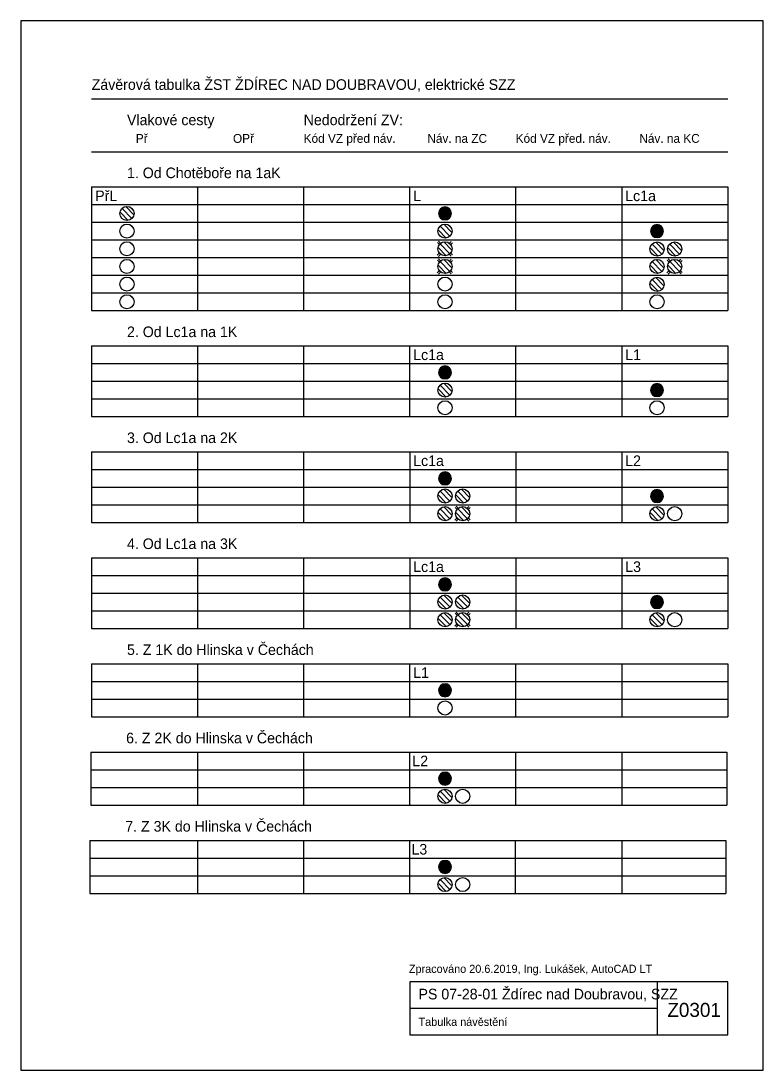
# Model space of a CAD drawing. Extents: x 2343 to 5155, y -3940 to 2050.
# Drawn here: x 3920 to 4130, y -3940 to -3643 of the extents above; entities that cross this region are included whole.
import ezdxf

# ---------------------------------------------------------------- set-up
doc = ezdxf.new("R2010")
doc.units = 0
for name, color, linetype in [('0B', 7, 'Continuous'), ('Implicitní', 7, 'Continuous'), ('Vrstva 63', 7, 'Continuous')]:
    doc.layers.add(name, color=color, linetype=linetype)

# ---------------------------------------------------------------- blocks, each defined once
blk = doc.blocks.new('ZT75')
at = {"layer": 'Implicitní'}
for points in [[(-18.1, 3.2), (18.1, 3.2)], [(-17.6, 0.7), (17.6, 0.7)], [(-17.3, 6.4), (17.3, 6.4)], [(-15.7, 9.6), (15.7, 9.6)], [(-14, 12), (14, 12)], [(-12.4, 13.6), (12.4, 13.6)], [(-10.4, 15.2), (10.4, 15.2)], [(-7.6, 16.8), (7.6, 16.8)], [(-18.1, -3.2), (18.1, -3.2)], [(-17.6, -0.7), (17.6, -0.7)], [(-17.3, -6.4), (17.3, -6.4)], [(-15.7, -9.6), (15.7, -9.6)], [(-14, -12), (14, -12)], [(-12.4, -13.6), (12.4, -13.6)], [(-10.4, -15.2), (10.4, -15.2)], [(-7.6, -16.8), (7.6, -16.8)]]:
    blk.add_lwpolyline(points, dxfattribs=at)
for start, end in [(0, 180), (180, 0)]:
    blk.add_arc((0, 0), 18.4, start, end, dxfattribs=at)
blk = doc.blocks.new('ZT76')
at = {"layer": 'Implicitní'}
for p, q in [((3.7, 19.7), (-19.7, -3.7)), ((14.1, 14.1), (-14.1, -14.1)), ((19.7, 3.7), (-3.7, -19.7))]:
    blk.add_line(p, q, dxfattribs=at)
blk.add_circle((0, 0), 20, dxfattribs=at)
blk = doc.blocks.new('ZT74')
at = {"layer": 'Implicitní'}
blk.add_circle((0, 0), 20, dxfattribs=at)
blk = doc.blocks.new('ZT78')
at = {"layer": 'Implicitní'}
for p, q in [((-30.7, 25.7), (-22.7, 17.7)), ((-25.7, 30.7), (-17.7, 22.7)), ((17.5, 21.7), (25.5, 29.7)), ((22.5, 16.7), (30.5, 24.7)), ((-31.3, -25.5), (-23.3, -17.5)), ((-26.3, -30.5), (-18.3, -22.5)), ((17.5, -21.7), (25.5, -29.7)), ((22.5, -16.7), (30.5, -24.7))]:
    blk.add_line(p, q, dxfattribs=at)

msp = doc.modelspace()

# ---------------------------------------------------------------- linework, layer by layer
at = {"layer": '0B'}
for p, q in [((3940, -3665), (4120, -3665)), ((3940, -3680), (4120, -3680)), ((3940, -3690), (4120, -3690)), ((3940, -3690), (3940, -3725)), ((3970, -3690), (3970, -3725)), ((4000, -3690), (4000, -3725)), ((4030, -3725), (4030, -3690)), ((4060, -3725), (4060, -3690)), ((4090, -3690), (4090, -3725)), ((4120, -3690), (4120, -3725)), ((3940, -3695), (4120, -3695)), ((3940, -3700), (4120, -3700)), ((3940, -3705), (4120, -3705)), ((3940, -3705), (4120, -3705)), ((3940, -3710), (4120, -3710)), ((3940, -3715), (4120, -3715)), ((3940, -3720), (4120, -3720)), ((3940, -3725), (4120, -3725)), ((3940, -3735), (4120, -3735)), ((3940, -3735), (3940, -3755)), ((3970, -3735), (3970, -3755)), ((4000, -3735), (4000, -3755)), ((4030, -3755), (4030, -3735)), ((4060, -3755), (4060, -3735)), ((4090, -3735), (4090, -3755)), ((4120, -3735), (4120, -3755)), ((3940, -3740), (4120, -3740)), ((3940, -3745), (4120, -3745)), ((3940, -3750), (4120, -3750)), ((3940, -3750), (4120, -3750)), ((3940, -3755), (4120, -3755)), ((3940, -3765), (4120, -3765)), ((3940, -3765), (3940, -3785)), ((3970, -3765), (3970, -3785)), ((4000, -3765), (4000, -3785)), ((4030, -3765), (4030, -3785)), ((4060, -3765), (4060, -3785)), ((4090, -3765), (4090, -3785)), ((4120, -3765), (4120, -3785)), ((3940, -3770), (4120, -3770)), ((3940, -3770), (4120, -3770)), ((3940, -3775), (4120, -3775)), ((3940, -3780), (4120, -3780)), ((3940, -3780), (4120, -3780)), ((3940, -3785), (4120, -3785)), ((3940, -3785), (4120, -3785)), ((3940, -3785), (4120, -3785)), ((3940, -3795), (4120, -3795)), ((3940, -3795), (3940, -3815)), ((3970, -3795), (3970, -3815)), ((4000, -3795), (4000, -3815)), ((4030, -3795), (4030, -3815)), ((4060, -3795), (4060, -3815)), ((4090, -3795), (4090, -3815)), ((4120, -3795), (4120, -3815)), ((3940, -3800), (4120, -3800)), ((3940, -3800), (4120, -3800)), ((3940, -3805), (4120, -3805)), ((3940, -3810), (4120, -3810)), ((3940, -3810), (4120, -3810)), ((3940, -3815), (4120, -3815)), ((3940, -3815), (4120, -3815)), ((3940, -3815), (4120, -3815)), ((3940, -3825), (4120, -3825)), ((3940, -3825), (3940, -3840)), ((3970, -3825), (3970, -3840)), ((4000, -3825), (4000, -3840)), ((4030, -3840), (4030, -3825)), ((4060, -3840), (4060, -3825)), ((4090, -3825), (4090, -3840)), ((4120, -3825), (4120, -3840)), ((3940, -3830), (4120, -3830)), ((3940, -3835), (4120, -3835)), ((3940, -3840), (4120, -3840)), ((3940, -3840), (4120, -3840)), ((3939.75, -3850), (4119.75, -3850)), ((3939.75, -3850), (3939.75, -3865)), ((3970, -3850), (3970, -3865)), ((4000, -3850), (4000, -3865)), ((4030, -3865), (4030, -3850)), ((4060, -3865), (4060, -3850)), ((4090, -3850), (4090, -3865)), ((4119.75, -3850), (4119.75, -3865)), ((3939.75, -3855), (4119.75, -3855)), ((3939.75, -3860), (4119.75, -3860)), ((3939.75, -3865), (4119.75, -3865)), ((3939.75, -3865), (4119.75, -3865)), ((3939.51, -3875), (4119.51, -3875)), ((3939.51, -3875), (3939.51, -3890)), ((3970, -3875), (3970, -3890)), ((4000, -3875), (4000, -3890)), ((4030, -3890), (4030, -3875)), ((4059.99, -3890), (4059.99, -3875)), ((4090, -3875), (4090, -3890)), ((4119.51, -3875), (4119.51, -3890)), ((3939.51, -3880), (4119.51, -3880)), ((3939.51, -3885), (4119.51, -3885)), ((3939.51, -3890), (4119.51, -3890)), ((3939.51, -3890), (4119.51, -3890)), ((4120, -3915), (4030, -3915)), ((4030, -3915), (4030, -3930)), ((4100, -3915), (4100, -3930)), ((4120, -3930), (4120, -3915)), ((4030, -3922.5), (4100, -3922.5)), ((4030, -3930), (4120, -3930))]:
    msp.add_line(p, q, dxfattribs=at)
at = {"layer": 'Vrstva 63'}
msp.add_lwpolyline([(3920, -3940), (4130, -3940), (4130, -3643), (3920, -3643)], close=True, dxfattribs=at)

# ---------------------------------------------------------------- block references
at = {"layer": '0B'}
for name, p, xscale, yscale, rotation in [('ZT76', (3950, -3697.5), 0.10000000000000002, 0.1, 89.99999999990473), ('ZT75', (4040, -3697.5), 0.1, 0.10000000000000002, -9.526953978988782e-11), ('ZT74', (3950, -3702.5), 0.1, 0.10000000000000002, -9.526953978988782e-11), ('ZT76', (4040, -3702.5), 0.10000000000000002, 0.1, 89.99999999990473), ('ZT75', (4100, -3702.5), 0.1, 0.10000000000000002, -9.526953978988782e-11), ('ZT74', (3950, -3707.5), 0.1, 0.10000000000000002, -9.526953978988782e-11), ('ZT78', (4040, -3707.5), 0.06999999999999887, 0.06999999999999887, -1.2050326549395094e-10), ('ZT76', (4040, -3707.5), 0.10000000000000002, 0.10000000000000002, 89.99999999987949), ('ZT76', (4100, -3707.57), 0.10000000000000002, 0.10000000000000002, 89.99999999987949), ('ZT76', (4105, -3707.57), 0.10000000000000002, 0.10000000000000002, 89.99999999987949), ('ZT74', (3950, -3712.5), 0.1, 0.10000000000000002, -9.526953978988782e-11), ('ZT78', (4040, -3712.5), 0.06999999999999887, 0.06999999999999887, -1.2050326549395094e-10), ('ZT76', (4040, -3712.5), 0.10000000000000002, 0.10000000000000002, 89.99999999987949), ('ZT76', (4040, -3712.5), 0.10000000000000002, 0.10000000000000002, 89.99999999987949), ('ZT76', (4100, -3712.5), 0.10000000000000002, 0.10000000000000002, 89.99999999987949), ('ZT78', (4105, -3712.5), 0.06999999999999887, 0.06999999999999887, -1.2050326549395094e-10), ('ZT76', (4105, -3712.5), 0.10000000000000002, 0.10000000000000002, 89.99999999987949), ('ZT76', (4105, -3712.5), 0.10000000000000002, 0.10000000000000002, 89.99999999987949), ('ZT74', (3950, -3717.5), 0.1, 0.10000000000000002, -9.526953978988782e-11), ('ZT74', (4040, -3717.5), 0.1, 0.10000000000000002, -9.526953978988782e-11), ('ZT76', (4100, -3717.57), 0.10000000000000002, 0.10000000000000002, 89.99999999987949), ('ZT74', (3950, -3722.5), 0.1, 0.10000000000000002, -9.526953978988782e-11), ('ZT74', (4040, -3722.5), 0.1, 0.10000000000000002, -9.526953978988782e-11), ('ZT74', (4100, -3722.5), 0.1, 0.10000000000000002, -9.526953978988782e-11), ('ZT75', (4040, -3742.5), 0.1, 0.10000000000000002, -9.526953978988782e-11), ('ZT76', (4040, -3747.5), 0.10000000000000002, 0.1, 89.99999999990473), ('ZT75', (4100, -3747.5), 0.1, 0.10000000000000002, -9.526953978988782e-11), ('ZT74', (4040, -3752.5), 0.1, 0.10000000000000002, -9.526953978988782e-11), ('ZT74', (4100, -3752.5), 0.1, 0.10000000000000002, -9.526953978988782e-11), ('ZT75', (4040, -3772.5), 0.1, 0.10000000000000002, -1.2050326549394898e-10), ('ZT76', (4040, -3777.5), 0.10000000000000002, 0.10000000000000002, 89.99999999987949), ('ZT76', (4045, -3777.5), 0.10000000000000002, 0.10000000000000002, 89.99999999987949), ('ZT76', (4045, -3777.5), 0.10000000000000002, 0.10000000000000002, 89.99999999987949), ('ZT75', (4100, -3777.5), 0.1, 0.10000000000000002, -1.2050326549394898e-10), ('ZT76', (4040, -3782.5), 0.10000000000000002, 0.10000000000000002, 89.99999999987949), ('ZT78', (4045, -3782.5), 0.06999999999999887, 0.06999999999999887, -1.2050326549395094e-10), ('ZT76', (4045, -3782.5), 0.10000000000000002, 0.10000000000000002, 89.99999999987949), ('ZT76', (4045, -3782.5), 0.10000000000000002, 0.10000000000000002, 89.99999999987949), ('ZT76', (4100, -3782.5), 0.10000000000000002, 0.10000000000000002, 89.99999999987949), ('ZT74', (4105, -3782.5), 0.1, 0.10000000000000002, -1.2050326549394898e-10), ('ZT75', (4040, -3802.5), 0.1, 0.10000000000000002, -1.2050326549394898e-10), ('ZT76', (4040, -3807.5), 0.10000000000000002, 0.10000000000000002, 89.99999999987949), ('ZT76', (4045, -3807.5), 0.10000000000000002, 0.10000000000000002, 89.99999999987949), ('ZT76', (4045, -3807.5), 0.10000000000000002, 0.10000000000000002, 89.99999999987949), ('ZT75', (4100, -3807.5), 0.1, 0.10000000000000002, -1.2050326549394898e-10), ('ZT76', (4040, -3812.5), 0.10000000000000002, 0.10000000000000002, 89.99999999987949), ('ZT78', (4045, -3812.5), 0.06999999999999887, 0.06999999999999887, -1.2050326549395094e-10), ('ZT76', (4045, -3812.5), 0.10000000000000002, 0.10000000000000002, 89.99999999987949), ('ZT76', (4045, -3812.5), 0.10000000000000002, 0.10000000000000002, 89.99999999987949), ('ZT76', (4100, -3812.5), 0.10000000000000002, 0.10000000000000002, 89.99999999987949), ('ZT74', (4105, -3812.5), 0.1, 0.10000000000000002, -1.2050326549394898e-10), ('ZT75', (4040, -3832.5), 0.1, 0.10000000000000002, -1.2050326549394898e-10), ('ZT74', (4040, -3837.5), 0.1, 0.10000000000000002, -1.2050326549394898e-10), ('ZT75', (4040, -3857.5), 0.1, 0.10000000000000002, -1.2050326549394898e-10), ('ZT76', (4040, -3862.5), 0.10000000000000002, 0.10000000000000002, 89.99999999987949), ('ZT74', (4045, -3862.5), 0.1, 0.10000000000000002, -1.2050326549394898e-10), ('ZT75', (4040, -3882.5), 0.1, 0.10000000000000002, -1.2050326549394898e-10), ('ZT76', (4040, -3887.5), 0.10000000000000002, 0.10000000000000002, 89.99999999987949), ('ZT74', (4045, -3887.5), 0.1, 0.10000000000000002, -1.2050326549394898e-10)]:
    msp.add_blockref(name, p, dxfattribs=dict(at, xscale=xscale, yscale=yscale, rotation=rotation))

# ---------------------------------------------------------------- texts
for s, height, p in [('Závěrová tabulka ŽST ŽDÍREC NAD DOUBRAVOU, elektrické SZZ', 3, (3940, -3662.5)), ('Vlakové cesty', 3, (3950, -3672.5)), ('Nedodržení ZV:', 3, (4000, -3672.5)), ('Př', 2.5, (3952.5, -3677.5)), ('OPř', 2.5, (3980, -3677.5)), ('Kód VZ před náv.', 2.5, (4000, -3677.5)), ('Náv. na ZC', 2.5, (4035, -3677.5)), ('Kód VZ před. náv.', 2.5, (4060, -3677.5)), ('Náv. na KC', 2.5, (4095, -3677.5)), ('1. Od Chotěboře na 1aK', 3, (3950, -3687.5)), ('PřL', 3, (3941, -3694)), ('L', 3, (4031, -3694)), ('Lc1a', 3, (4091, -3694)), ('2. Od Lc1a na 1K', 3, (3950, -3732.5)), ('Lc1a', 3, (4031, -3739)), ('L1', 3, (4091, -3739)), ('3. Od Lc1a na 2K', 3, (3950, -3762.5)), ('L2', 3, (4091, -3769)), ('Lc1a', 3, (4031, -3769)), ('4. Od Lc1a na 3K', 3, (3950, -3792.5)), ('Lc1a', 3, (4031, -3799)), ('L3', 3, (4091, -3799)), ('5. Z 1K do Hlinska v Čechách', 3, (3950, -3822.5)), ('L1', 3, (4031, -3829)), ('6. Z 2K do Hlinska v Čechách', 3, (3949.75, -3847.5)), ('L2', 3, (4030.75, -3854)), ('7. Z 3K do Hlinska v Čechách', 3, (3949.51, -3872.5)), ('L3', 3, (4030.51, -3879)), ('Zpracováno 20.6.2019, Ing. Lukášek, AutoCAD LT', 2.2988, (4029.77, -3912.5)), ('PS 07-28-01 Ždírec nad Doubravou, SZZ', 3, (4032.5, -3920)), ('Z0301', 4, (4102.92, -3924.98)), ('Tabulka návěstění', 2.3, (4032.5, -3927.5))]:
    msp.add_text(s, height=height, rotation=360, dxfattribs=at).set_placement(p)

doc.saveas('drawing.dxf')
